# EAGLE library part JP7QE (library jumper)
JUMPER
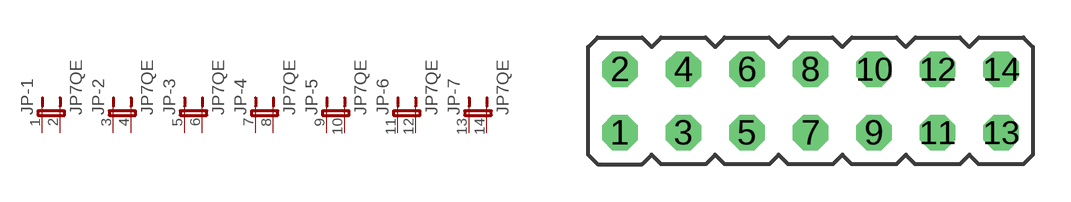
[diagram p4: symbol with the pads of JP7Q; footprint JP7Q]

Designator prefix JP; gates -1=JP2E -2=JP2E -3=JP2E -4=JP2E -5=JP2E -6=JP2E -7=JP2E

## JP7QE  [JP7Q]
1  -1:1  pas
2  -1:2  pas
3  -2:1  pas
4  -2:2  pas
5  -3:1  pas
6  -3:2  pas
7  -4:1  pas
8  -4:2  pas
9  -5:1  pas
10  -5:2  pas
11  -6:1  pas
12  -6:2  pas
13  -7:1  pas
14  -7:2  pas

## Footprint JP7Q (pad centres in mm)
JUMPER
drill 0.914 octagon: 1 -7.62,-1.27; 2 -7.62,1.27; 3 -5.08,-1.27; 4 -5.08,1.27; 5 -2.54,-1.27; 6 -2.54,1.27; 7 0,-1.27; 8 0,1.27; 9 2.54,-1.27; 10 2.54,1.27; 11 5.08,-1.27; 12 5.08,1.27; 13 7.62,-1.27; 14 7.62,1.27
